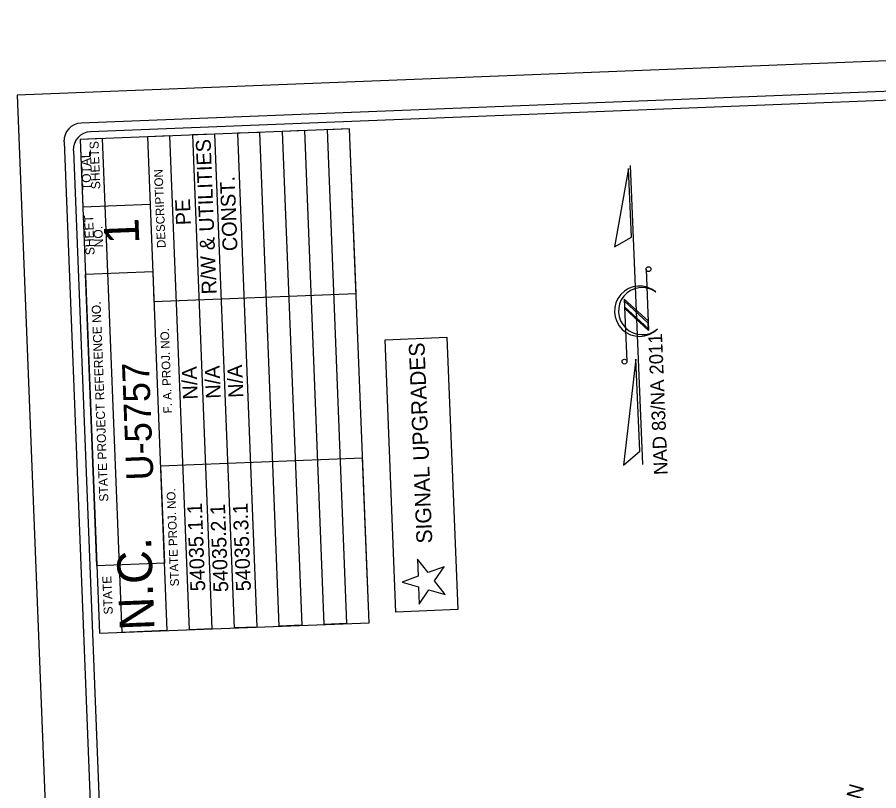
# Model space of a CAD drawing. Extents: x 1624323 to 1631382, y 753034 to 769560.
# Drawn here: x 1624323 to 1627225, y 765176 to 767782 of the extents above; entities that cross this region are included whole.
import ezdxf

# ---------------------------------------------------------------- set-up
doc = ezdxf.new("R2010")
doc.units = 0
for name, color, linetype in [('Prop DSN Text', 7, 'Continuous'), ('Prop Grid Mask', 7, 'Continuous'), ('Prop RDY Traffic Signal CELL', 7, 'Continuous'), ('Sheet Data Field CELL', 7, 'Continuous'), ('Sheet North Arrow CELL', 7, 'Continuous'), ('Sheet Plot Border Outside CELL', 7, 'Continuous'), ('Sheet Title CELL', 7, 'Continuous')]:
    doc.layers.add(name, color=color, linetype=linetype)

msp = doc.modelspace()

# ---------------------------------------------------------------- linework, layer by layer
at = {"layer": 'Prop Grid Mask'}
msp.add_lwpolyline([(1625598.6, 765778), (1625562.4, 766695.5), (1625770.6, 766703.7), (1625806.8, 765786.2)], close=True, dxfattribs=at)
at = {"layer": 'Prop RDY Traffic Signal CELL'}
msp.add_lwpolyline([(1625675, 765862.6), (1625677.3, 765805), (1625709.3, 765853), (1625764.9, 765837.3), (1625729.1, 765882.7), (1625761.2, 765930.7), (1625707, 765910.7), (1625671.3, 765956), (1625673.6, 765898.3), (1625619.4, 765878.3), (1625675, 765862.6)], dxfattribs=at)
at = {"layer": 'Sheet North Arrow CELL'}
for p, q in [((1626430, 766275.1), (1626388.9, 767282.2)), ((1626441.1, 766933.3), (1626449.6, 766726.6)), ((1626448.3, 766758.8), (1626368.1, 766832.7)), ((1626368.1, 766832.7), (1626376.7, 766622.6)), ((1626472.8, 766857.4), (1626473.9, 766856.7)), ((1626448.6, 766751.2), (1626368.4, 766825.1)), ((1626368.4, 766825.1), (1626369.2, 766806.2)), ((1626449.3, 766732.3), (1626369.2, 766806.2)), ((1626369.2, 766806.2), (1626449.3, 766732.3)), ((1626449.6, 766726.6), (1626369.4, 766800.5)), ((1626449.3, 766732.3), (1626448.6, 766751.2))]:
    msp.add_line(p, q, dxfattribs=at)
for points in [[(1626382.3, 767273.1), (1626335.5, 767009.2), (1626391.7, 767040.7)], [(1626407.3, 766629.6), (1626364.8, 766272.5), (1626420, 766319.7)]]:
    msp.add_lwpolyline(points, close=True, dxfattribs=at)
for centre in [(1626449.4, 766933.5), (1626368.5, 766621.9)]:
    msp.add_circle(centre, 8.22, dxfattribs=at)
for centre, radius, start, end in [((1626419.6, 766791.7), 84.7, 50.1787, 314.7327), ((1626427.8, 766792.1), 79.4, 55.4337, 310.9674)]:
    msp.add_arc(centre, radius, start, end, dxfattribs=at)
at = {"layer": 'Sheet Plot Border Outside CELL'}
msp.add_lwpolyline([(1624322.9, 767519.9), (1624724.8, 757327.8), (1631382.3, 757590.3), (1630980.3, 767782.4)], close=True, dxfattribs=at)
at = {"layer": 'Sheet Title CELL'}
for points in [[(1630772.6, 767671.2), (1624538.8, 767425.4)], [(1629623.9, 767595.6), (1624570.2, 767396.3)], [(1625508.3, 765742.1), (1625442.6, 767406.4), (1625367.1, 767403.5), (1625432.6, 765739.1), (1625357, 765736.1), (1625291.4, 767400.5), (1625215.8, 767397.5), (1625281.4, 765733.2), (1625205.7, 765730.1), (1625140, 767394.5), (1625064.4, 767391.5), (1625130, 765727.1), (1625054.4, 765724.2), (1624988.7, 767388.5), (1624913.1, 767385.6), (1624978.8, 765721.2), (1624903.1, 765718.2), (1624837.5, 767382.6), (1624761.8, 767379.6), (1624827.4, 765715.2), (1624676.1, 765709.3), (1624610.5, 767373.6), (1624534.8, 767370.7), (1624600.5, 765706.3), (1625508.3, 765742.1), (1625486.5, 766296.8), (1624805.6, 766269.9), (1624818.5, 765942.2), (1624591.5, 765933.2), (1624552.8, 766916.8), (1624779.7, 766925.7), (1624783.6, 766824.6), (1625464.5, 766851.5), (1625442.6, 767406.4), (1624534.8, 767370.7), (1624543.7, 767143.7), (1624770.7, 767152.7)], [(1624480.6, 767362.5), (1624833.8, 758405)], [(1624512.1, 767333.4), (1624851, 758739.2)]]:
    msp.add_lwpolyline(points, dxfattribs=at)
for centre in [(1624540.8, 767364.9), (1624572.3, 767335.8)]:
    msp.add_arc(centre, 60.6, 92.2582, 182.2582, dxfattribs=at)

# ---------------------------------------------------------------- texts
at = {"layer": 'Prop DSN Text'}
for s, height, rotation, p in [('SIGNAL UPGRADES', 52.999, 92.2582, (1625721.3, 766010)), ('LEXINGTON', 50, 74.4686, (1627073.1, 764817.5))]:
    msp.add_text(s, height=height, rotation=rotation, dxfattribs=at).set_placement(p)
at = {"layer": 'Sheet Data Field CELL'}
for s, height, p in [('R/W & UTILITIES', 50, (1624994.7, 766849.4)), ('CONST.', 50, (1625065.2, 766995.1)), ('PE', 50, (1624908, 767082.6)), ('U-5757', 90.86, (1624782, 766223.3)), ('N/A', 50, (1624931.2, 766494.9)), ('N/A', 50, (1625008.6, 766497.9)), ('N/A', 50, (1625084.7, 766500.9)), ('54035.1.1', 50, (1624956.6, 765848.9)), ('54035.2.1', 50, (1625034.3, 765846)), ('54035.3.1', 50, (1625110.4, 765849))]:
    msp.add_text(s, height=height, rotation=92.2582, dxfattribs=at).set_placement(p)
at = {"layer": 'Sheet North Arrow CELL'}
msp.add_text('NAD 83/NA 2011', height=46.518, rotation=92.3387, dxfattribs=at).set_placement((1626514.4, 766240.9))
at = {"layer": 'Sheet Title CELL'}
for s, height, p in [('SHEETS', 30.28, (1624602.9, 767203.5)), ('TOTAL', 30.28, (1624572.7, 767200.3)), ('DESCRIPTION', 29.074, (1624823, 767005.3)), ('SHEET', 30.28, (1624583.6, 766981.3)), ('1', 117.2, (1624734.4, 767020)), ('NO.', 30.28, (1624612.5, 767007.6)), ('STATE PROJECT REFERENCE NO.', 30.284, (1624630, 766150.5)), ('F. A. PROJ. NO.', 29.074, (1624844.9, 766447.9)), ('STATE PROJ. NO.', 29.074, (1624867.9, 765865)), ('N.C.', 117.2, (1624785.8, 765718.1)), ('STATE', 30.28, (1624644.9, 765770.2))]:
    msp.add_text(s, height=height, rotation=92.2582, dxfattribs=at).set_placement(p)

doc.saveas('drawing.dxf')
